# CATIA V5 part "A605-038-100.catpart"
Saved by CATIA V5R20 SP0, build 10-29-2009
Part number: A605-038-100
Source: Unknown
Property "A": "0.000"
Property "ARTICLENO": "A605-038-100"
Property "BOMINFO": "A605-038-100"
Property "CODE": "A605-038-100"
Property "D": "9.000"
Property "FORM": "A"
Property "L": "100.000"
Property "L1": "70.000"
Property "LINA": "A605-038-100"
Property "NB": "A605-038-100"
Property "NBSYN": "$CODE."
Property "NN": "A605"
Property "NT": "Wear Plates, self-lubricating"
Property "SCREW": "2*M8X16"
Property "SUPPLIER": "CF"
Property "W": "38.000"
Bounding box of the stored display mesh (mm): x -38 to 0, y 0 to 5, z -100 to 0
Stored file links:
  C:\Users\Utente\Desktop\3D files A605\A605-038-100.catpart
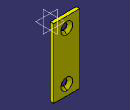
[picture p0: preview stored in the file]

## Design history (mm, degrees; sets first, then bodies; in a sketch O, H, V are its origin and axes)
Body1 "Geometry.1" (main body)
  Solid1 "A605-038-100.catpart": solid without history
